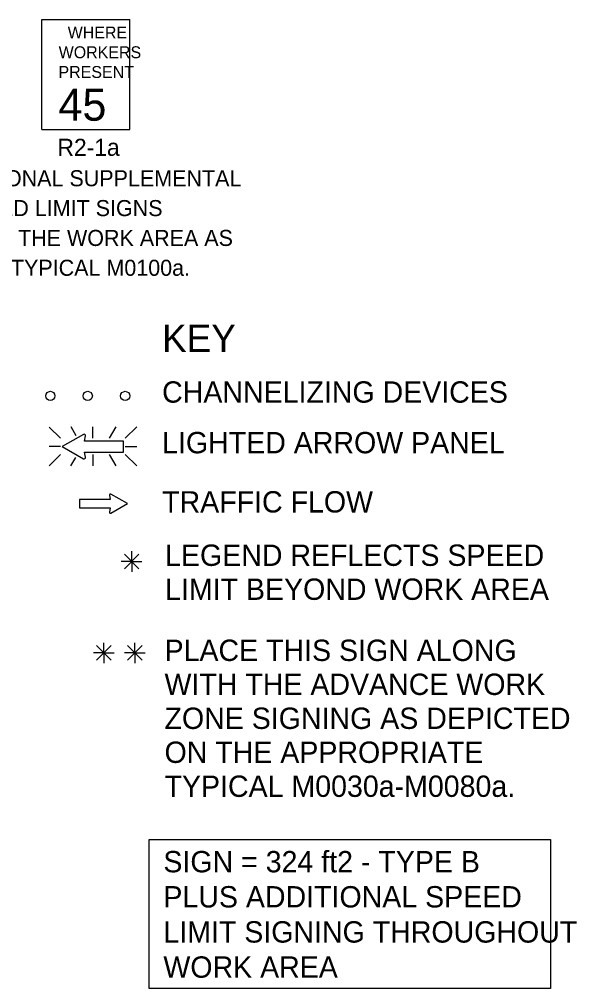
# Model space of a CAD drawing. Extents: x 16726 to 18475, y 5752 to 6929.
# Drawn here: x 17184.6 to 17427.4, y 6414.9 to 6837.1 of the extents above; entities that cross this region are included whole.
import ezdxf

# ---------------------------------------------------------------- set-up
doc = ezdxf.new("R2010")
doc.units = 0
for name, color, linetype in [('MT_SCRATCH_LEVEL_E', 7, 'Continuous'), ('TRAFFIC_SIGNS_PR', 7, 'Continuous'), ('TYPICAL_TEXT_DIMEN_EX', 7, 'Continuous'), ('TYPICAL_TEXT_DIMEN_PR', 7, 'Continuous')]:
    doc.layers.add(name, color=color, linetype=linetype)

msp = doc.modelspace()

# ---------------------------------------------------------------- linework, layer by layer
at = {"layer": 'MT_SCRATCH_LEVEL_E'}
for p, q in [((17223.84, 6629.79), (17224.15, 6628.01)), ((17231.76, 6626.16), (17224.52, 6630.27)), ((17224.15, 6628.01), (17210.89, 6628.01)), ((17210.89, 6628.01), (17210.89, 6624.27)), ((17224.52, 6622.02), (17231.76, 6626.16)), ((17210.89, 6624.27), (17224.15, 6624.27)), ((17224.15, 6624.27), (17223.84, 6622.49))]:
    msp.add_line(p, q, dxfattribs=at)
for centre, start, end in [((17224.29, 6629.87), 60.4248, 189.9638), ((17224.29, 6622.42), 170.0362, 299.7731)]:
    msp.add_arc(centre, 0.463, start, end, dxfattribs=at)
at = {"layer": 'TRAFFIC_SIGNS_PR'}
for p, q in [((17194.38, 6837.1), (17232.78, 6837.1)), ((17194.38, 6789.1), (17194.38, 6837.1)), ((17232.78, 6789.1), (17232.78, 6837.1)), ((17194.38, 6789.1), (17232.78, 6789.1)), ((17197.57, 6659.54), (17202.5, 6654.61)), ((17209.33, 6655.72), (17207.13, 6659.55)), ((17216.65, 6654.61), (17216.65, 6659.55)), ((17223.89, 6654.61), (17226.74, 6659.55)), ((17230.8, 6654.61), (17235.74, 6659.55)), ((17202.5, 6651.06), (17197.57, 6651.06)), ((17230.8, 6651.06), (17235.74, 6651.06)), ((17197.57, 6642.57), (17202.5, 6647.5)), ((17207.08, 6642.57), (17209.2, 6646.23)), ((17216.65, 6647.5), (17216.65, 6642.57)), ((17226.78, 6642.57), (17223.93, 6647.5)), ((17230.8, 6647.5), (17235.74, 6642.56))]:
    msp.add_line(p, q, dxfattribs=at)
for points in [[(17212.58, 6656.33), (17203.29, 6651.06), (17212.58, 6645.74)], [(17213.46, 6646.36), (17213.06, 6648.63), (17230.07, 6648.63), (17230.07, 6653.43), (17213.06, 6653.43), (17213.46, 6655.71)]]:
    msp.add_lwpolyline(points, dxfattribs=at)
for centre in [(17198.13, 6673.09), (17214.43, 6673.09), (17230.73, 6673.09)]:
    msp.add_circle(centre, 2, dxfattribs=at)
for centre, radius, start, end in [((17212.87, 6655.81), 0.598, 350.7308, 118.8916), ((17212.87, 6646.26), 0.597, 241.4833, 9.9593)]:
    msp.add_arc(centre, radius, start, end, dxfattribs=at)
at = {"layer": 'TYPICAL_TEXT_DIMEN_EX'}
msp.add_lwpolyline([(17241.15, 6479.8), (17416.07, 6479.8), (17416.07, 6414.9), (17241.15, 6414.9)], close=True, dxfattribs=at)
at = {"layer": 'TYPICAL_TEXT_DIMEN_PR'}
for p, q in [((17230.38, 6604.12), (17236.75, 6597.75)), ((17236.75, 6604.12), (17230.38, 6597.75)), ((17233.57, 6600.94), (17233.57, 6605.39)), ((17233.57, 6600.94), (17229.03, 6600.94)), ((17233.57, 6600.94), (17236.75, 6600.94)), ((17233.57, 6600.94), (17238.04, 6600.94)), ((17233.57, 6600.94), (17233.57, 6596.44)), ((17221.43, 6561.12), (17221.43, 6565.57)), ((17234.93, 6561.12), (17234.93, 6565.57)), ((17221.43, 6561.12), (17216.89, 6561.12)), ((17218.24, 6564.31), (17224.61, 6557.93)), ((17224.61, 6564.31), (17218.24, 6557.93)), ((17221.43, 6561.12), (17224.61, 6561.12)), ((17221.43, 6561.12), (17225.9, 6561.12)), ((17221.43, 6561.12), (17221.43, 6556.62)), ((17234.93, 6561.12), (17230.4, 6561.12)), ((17238.12, 6564.31), (17231.74, 6557.93)), ((17231.75, 6564.31), (17238.12, 6557.93)), ((17234.93, 6561.12), (17238.12, 6561.12)), ((17234.93, 6561.12), (17239.41, 6561.12)), ((17234.93, 6561.12), (17234.93, 6556.62))]:
    msp.add_line(p, q, dxfattribs=at)

# ---------------------------------------------------------------- texts
at = {"layer": 'TRAFFIC_SIGNS_PR'}
for s, height, p in [('WHERE', 5.2, (17205.69, 6828.78)), ('WORKERS', 5.2, (17201.76, 6820.18)), ('PRESENT', 5.2, (17201.69, 6811.58)), ('45', 14.031, (17201.68, 6792.96)), ('R2-1a', 7.44, (17201.23, 6777.66)), ('PLACE ADDITIONAL SUPPLEMENTAL', 7, (17114.38, 6764.4)), ('SETS OF SPEED LIMIT SIGNS', 7, (17114.38, 6751.4)), ('THROUGHOUT THE WORK AREA AS', 7, (17114.38, 6738.4)), ('DEPICTED ON TYPICAL M0100a.', 7, (17114.38, 6725.4))]:
    msp.add_text(s, height=height, dxfattribs=at).set_placement(p)
at = {"layer": 'TYPICAL_TEXT_DIMEN_EX'}
for s, height, p in [('KEY', 12, (17246.83, 6692.19)), ('CHANNELIZING DEVICES', 9.3, (17246.83, 6670.14)), ('LIGHTED ARROW PANEL', 9.3, (17246.83, 6648.09)), ('TRAFFIC FLOW', 9.3, (17246.83, 6622.29)), ('LEGEND REFLECTS SPEED', 9.3, (17248.12, 6599.04)), ('LIMIT BEYOND WORK AREA', 9.3, (17248.12, 6584.24)), ('PLACE THIS SIGN ALONG', 9.3, (17247.88, 6557.62)), ('WITH THE ADVANCE WORK', 9.3, (17247.88, 6542.82)), ('ZONE SIGNING AS DEPICTED', 9.3, (17247.88, 6528.02)), ('ON THE APPROPRIATE', 9.3, (17247.88, 6513.22)), ('TYPICAL M0030a-M0080a.', 9.3, (17247.88, 6498.42)), ('SIGN = 324 ft2 - TYPE B', 9.3, (17247.38, 6465.55)), ('PLUS ADDITIONAL SPEED', 9.3, (17247.38, 6450.25)), ('LIMIT SIGNING THROUGHOUT', 9.3, (17247.38, 6434.95)), ('WORK AREA', 9.3, (17247.38, 6419.65))]:
    msp.add_text(s, height=height, dxfattribs=at).set_placement(p)

doc.saveas('drawing.dxf')
